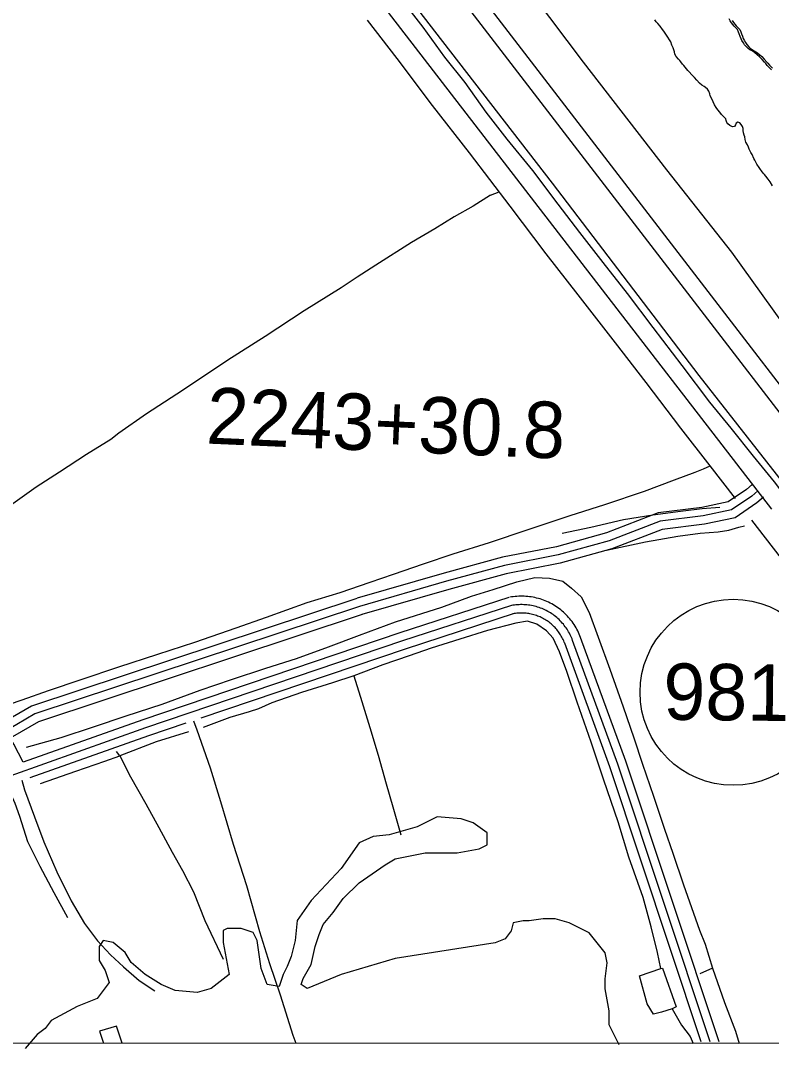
# Model space of a CAD drawing. Extents: x 3245246 to 3283090, y 806824 to 832173.
# Drawn here: x 3268806 to 3270136, y 812195 to 814018 of the extents above; entities that cross this region are included whole.
import ezdxf

# ---------------------------------------------------------------- set-up
doc = ezdxf.new("R2010")
doc.units = 0
for name, color, linetype in [('V-BORW-LINE', 7, 'Continuous'), ('V-GRID-FRAM', 7, 'Continuous'), ('V-LEVE-TOET', 7, 'Continuous'), ('V-ROAD-CNTR', 7, 'Continuous'), ('V-ROAD-IDEN', 7, 'Continuous'), ('V-SITE-STRC', 7, 'Continuous'), ('V-SITE-VEGE', 7, 'Continuous'), ('V-SURV-IDEN', 7, 'Continuous'), ('V-SURV-LINE', 7, 'Continuous'), ('V-TOPO-SHOR', 7, 'Continuous')]:
    doc.layers.add(name, color=color, linetype=linetype)

msp = doc.modelspace()

# ---------------------------------------------------------------- linework, layer by layer
at = {"layer": 'V-BORW-LINE'}
for points in [[(3270116.6, 813754.3), (3270114.5, 813757.4), (3270110.6, 813763.6), (3270107, 813770.4), (3270105.1, 813773.5), (3270101.8, 813780.6), (3270099.7, 813784.3), (3270096.9, 813790.2), (3270095.4, 813793.6), (3270093.6, 813797.9), (3270090.9, 813802.7), (3270089.9, 813807), (3270089.2, 813812.1), (3270087.7, 813815.2), (3270086.7, 813819.2), (3270086.3, 813823.5), (3270085.9, 813827), (3270084.7, 813830.4), (3270082.8, 813834.1), (3270079.9, 813837.1), (3270076.7, 813838.2), (3270073.9, 813836.4), (3270072.8, 813833.5), (3270070.9, 813830.6), (3270066.9, 813829.9), (3270062.2, 813831.8), (3270059, 813835.1), (3270056.9, 813837.4), (3270056, 813840.8), (3270055.3, 813843.9), (3270052.9, 813846.5), (3270050.3, 813849.3), (3270047.6, 813851.8), (3270044.7, 813855.7), (3270041.1, 813859.6), (3270038.4, 813863.9), (3270035.4, 813868.7), (3270033, 813873.8), (3270029.9, 813880.3), (3270027.8, 813884.8), (3270027.1, 813888), (3270025.3, 813892.8), (3270022.6, 813896.4), (3270019.4, 813899.2), (3270017, 813901.5), (3270012.9, 813903.9), (3270008.5, 813907.3), (3270003.8, 813912.3), (3269999.6, 813917.1), (3269997.6, 813919.6), (3269995.2, 813922.1), (3269990.2, 813927.4), (3269988.1, 813929.7), (3269985.4, 813932.8), (3269981, 813938.4), (3269978.6, 813940.9), (3269975.9, 813944.9), (3269973.9, 813947.1), (3269971.2, 813949.9), (3269967.1, 813954.4), (3269965.2, 813958.6), (3269964.2, 813962.6), (3269963, 813966), (3269961.8, 813969.7), (3269959.6, 813974.6), (3269958, 813980.5), (3269955.6, 813984.2), (3269952.3, 813989), (3269949, 813994.1), (3269945.5, 813999.4), (3269943.4, 814002.5), (3269938.9, 814008.5), (3269935, 814012.9), (3269932.1, 814016), (3269929.4, 814019.4)], [(3270066.7, 814018.2), (3270069.1, 814014.6), (3270073.8, 814008.9), (3270077.7, 814005), (3270080, 814002.5), (3270081.9, 813998), (3270083.1, 813994.8), (3270084.7, 813990.3), (3270086.2, 813986.3), (3270087.7, 813983.5), (3270090.4, 813979.2), (3270092.5, 813975.6), (3270096.4, 813971.4), (3270099, 813968.8), (3270101.9, 813966.6), (3270105.7, 813964.7), (3270109.8, 813962), (3270114.8, 813958.1), (3270118.9, 813954.2), (3270123.4, 813949.7), (3270127.8, 813944.6), (3270129.9, 813942.4), (3270132.6, 813939), (3270137.9, 813933.7)], [(3270138, 813725.3), (3270133.8, 813732.1), (3270130.2, 813737.1), (3270126.1, 813742.5), (3270124, 813745), (3270121.6, 813747.5), (3270118.7, 813751.8), (3270116.6, 813754.3)]]:
    msp.add_lwpolyline(points, dxfattribs=at)
at = {"layer": 'V-GRID-FRAM'}
msp.add_lwpolyline([(3249428.8, 830400), (3280833.3, 830386.3), (3280833.3, 812199.6), (3249412.9, 812213.3), (3249428.8, 830400)], dxfattribs=at)
at = {"layer": 'V-LEVE-TOET'}
for points in [[(3269309.8, 814296.6), (3269553.2, 813980.9), (3269747.4, 813729.8), (3270007.7, 813389), (3270212.9, 813126.4), (3270300.9, 813008.4), (3270316.5, 812980.3), (3270348.7, 812914.5), (3270515.4, 812529.7), (3270660.8, 812204)], [(3270853.7, 812203.9), (3270841.6, 812230.7), (3270740.7, 812469.9), (3270678, 812611.2), (3270607.7, 812771.2), (3270538.2, 812930.8), (3270513.8, 812999.4), (3270496.9, 813033), (3270482.6, 813057.4), (3270457.7, 813088.3), (3270385.9, 813179.7), (3270285.5, 813318.1), (3270193.6, 813429.3), (3270066.2, 813607.4), (3269950.8, 813753.5), (3269803.4, 813944.4), (3269654.7, 814141.9)]]:
    msp.add_lwpolyline(points, dxfattribs=at)
at = {"layer": 'V-ROAD-CNTR'}
for points in [[(3269299.2, 814237.7), (3269774.1, 813621.1), (3270136.2, 813151.8)], [(3270102, 813195.4), (3270092.1, 813186.5), (3270059.8, 813164.8), (3270012.8, 813154.8), (3269935.4, 813144.9), (3269844, 813110), (3269755, 813085.1), (3269659.5, 813066.3), (3269556.3, 813038.3), (3269402.1, 812993.6)], [(3270112.1, 813184.3), (3270101.3, 813174.6), (3270065.7, 813150.7), (3270015.3, 813140), (3269939.1, 813130.3), (3269848.7, 813095.8), (3269758.5, 813070.5), (3269662.9, 813051.7), (3269560.4, 813023.8), (3269406.3, 812979.2)], [(3270122.1, 813173.1), (3270110.6, 813162.7), (3270071.7, 813136.6), (3270017.8, 813125.2), (3269942.8, 813115.6), (3269853.4, 813081.5), (3269762, 813055.9), (3269666.3, 813037), (3269564.4, 813009.4), (3269410.5, 812964.8)], [(3269401.6, 812993.5), (3268824.9, 812802.2), (3268791.4, 812783), (3268758.5, 812764)], [(3269670.7, 812995), (3269477.9, 812932.2), (3269022.3, 812778), (3268810.4, 812702.8)], [(3269797.9, 812924.3), (3269796.8, 812927.1), (3269795.6, 812930), (3269794.3, 812933), (3269792.9, 812935.9), (3269791.4, 812938.7), (3269789.9, 812941.5), (3269788.2, 812944.3), (3269786.5, 812947), (3269784.7, 812949.6), (3269782.8, 812952.2), (3269780.9, 812954.8), (3269778.9, 812957.3), (3269776.8, 812959.7), (3269774.6, 812962.1), (3269772.4, 812964.4), (3269770.1, 812966.7), (3269767.8, 812968.8), (3269765.4, 812971), (3269762.9, 812973), (3269760.4, 812975), (3269757.8, 812976.9), (3269755.1, 812978.7), (3269752.4, 812980.4), (3269749.7, 812982.1), (3269746.9, 812983.7), (3269744.1, 812985.2), (3269741.2, 812986.6), (3269738.3, 812987.9), (3269735.3, 812989.2), (3269732.3, 812990.3), (3269729.3, 812991.4), (3269726.3, 812992.4), (3269723.2, 812993.3), (3269720.1, 812994.1), (3269717, 812994.9), (3269713.8, 812995.5), (3269710.6, 812996.1), (3269707.5, 812996.5), (3269704.3, 812996.9), (3269701.1, 812997.1), (3269697.9, 812997.3), (3269694.7, 812997.4), (3269691.5, 812997.4), (3269688.3, 812997.3), (3269685.1, 812997.1), (3269681.9, 812996.8), (3269678.7, 812996.4), (3269675.5, 812996), (3269672.7, 812995.5)], [(3269675.3, 812980.7), (3269482.6, 812918), (3269027.2, 812763.8), (3268727.9, 812657.6), (3268524, 812586.4), (3267985.6, 812407), (3267401, 812210.6)], [(3269406.3, 812979.2), (3268831, 812788.5), (3268798.9, 812770), (3268763.9, 812749.8)], [(3269680, 812966.4), (3269487.3, 812903.7), (3269125, 812781.1)], [(3269783.9, 812919), (3269782.9, 812921.5), (3269781.8, 812924.1), (3269780.7, 812926.6), (3269779.5, 812929.1), (3269778.2, 812931.6), (3269776.8, 812934), (3269775.4, 812936.4), (3269773.9, 812938.8), (3269772.4, 812941.1), (3269770.8, 812943.3), (3269769.1, 812945.5), (3269767.4, 812947.7), (3269765.5, 812949.8), (3269763.7, 812951.9), (3269761.8, 812953.9), (3269759.8, 812955.8), (3269757.7, 812957.7), (3269755.7, 812959.5), (3269753.5, 812961.3), (3269751.3, 812963), (3269749.1, 812964.6), (3269746.8, 812966.2), (3269744.5, 812967.7), (3269742.1, 812969.1), (3269739.7, 812970.5), (3269737.2, 812971.8), (3269734.7, 812973), (3269732.2, 812974.2), (3269729.7, 812975.3), (3269727.1, 812976.3), (3269724.5, 812977.2), (3269721.8, 812978.1), (3269719.2, 812978.9), (3269716.5, 812979.6), (3269713.8, 812980.2), (3269711, 812980.8), (3269708.3, 812981.2), (3269705.6, 812981.6), (3269702.8, 812981.9), (3269700, 812982.2), (3269697.3, 812982.3), (3269694.5, 812982.4), (3269691.7, 812982.4), (3269688.9, 812982.3), (3269686.2, 812982.1), (3269683.4, 812981.9), (3269680.7, 812981.6), (3269677.9, 812981.2), (3269675.3, 812980.7)], [(3269769.8, 812913.6), (3269768.9, 812916), (3269768, 812918.2), (3269767.1, 812920.3), (3269766.1, 812922.4), (3269765, 812924.5), (3269763.8, 812926.6), (3269762.6, 812928.6), (3269761.4, 812930.6), (3269760.1, 812932.5), (3269758.7, 812934.4), (3269757.3, 812936.3), (3269755.8, 812938.1), (3269754.3, 812939.9), (3269752.7, 812941.6), (3269751.1, 812943.3), (3269749.4, 812944.9), (3269747.7, 812946.5), (3269745.9, 812948.1), (3269744.1, 812949.6), (3269742.3, 812951), (3269740.4, 812952.4), (3269738.5, 812953.7), (3269736.5, 812955), (3269734.5, 812956.2), (3269732.5, 812957.4), (3269730.4, 812958.5), (3269728.3, 812959.5), (3269726.2, 812960.5), (3269724, 812961.4), (3269721.8, 812962.2), (3269719.6, 812963), (3269717.4, 812963.8), (3269715.1, 812964.4), (3269712.9, 812965), (3269710.6, 812965.6), (3269708.3, 812966), (3269706, 812966.4), (3269703.7, 812966.7), (3269701.3, 812967), (3269699, 812967.2), (3269696.7, 812967.3), (3269694.3, 812967.4), (3269692, 812967.4), (3269689.6, 812967.3), (3269687.3, 812967.2), (3269685, 812967), (3269682.6, 812966.7), (3269680.3, 812966.4), (3269677.9, 812965.9)], [(3269411, 812965), (3268837.2, 812774.7), (3268806.3, 812757), (3268787, 812745.8)], [(3270011.9, 812207), (3269850.1, 812694.7), (3269769.8, 812913.8)], [(3270027.7, 812207), (3269864.2, 812699.6), (3269783.9, 812919)], [(3270043.6, 812207), (3269878.4, 812704.6), (3269797.9, 812924.1)], [(3269098.3, 812772.1), (3269032.1, 812749.6), (3268822, 812675.1)], [(3269111.9, 812776.1), (3269117.6, 812760.6), (3269141.3, 812692.8), (3269160, 812633.1), (3269182, 812557.7), (3269205.8, 812484.2), (3269228.9, 812403), (3269246.4, 812345.8), (3269265.3, 812290.3), (3269287.9, 812219.1), (3269293.3, 812204.6)], [(3268810.4, 812702.8), (3268793.4, 812735.2), (3268787, 812745.8)], [(3268807.9, 812671.3), (3268812.7, 812654.1), (3268830.2, 812605.9), (3268847, 812561.6), (3268869.7, 812508.6), (3268895, 812457.2), (3268919, 812416.9), (3268942.1, 812386), (3268965, 812361.1), (3268988.1, 812339.8), (3269015.9, 812316.1), (3269043.2, 812297.6)]]:
    msp.add_lwpolyline(points, dxfattribs=at)
at = {"layer": 'V-ROAD-IDEN'}
msp.add_circle((3270068.4, 812827), 165, dxfattribs=at)
at = {"layer": 'V-SITE-STRC'}
msp.add_lwpolyline([(3268985.7, 812204.7), (3268975.4, 812235.1), (3268945.2, 812226.2), (3268952.6, 812204.8)], dxfattribs=at)
at = {"layer": 'V-SITE-VEGE'}
for p, q in [((3270062.8, 814017.8), (3270061.3, 814021.2)), ((3270065.2, 814014.1), (3270062.8, 814017.8)), ((3270070, 814008.5), (3270065.2, 814014.1)), ((3270073.8, 814004.6), (3270070, 814008.5)), ((3270076.2, 814002.1), (3270073.8, 814004.6)), ((3270078, 813997.5), (3270076.2, 814002.1)), ((3270079.2, 813994.4), (3270078, 813997.5)), ((3270080.8, 813989.8), (3270079.2, 813994.4)), ((3270082.3, 813985.9), (3270080.8, 813989.8)), ((3270083.8, 813983), (3270082.3, 813985.9)), ((3270086.5, 813978.8), (3270083.8, 813983)), ((3270088.7, 813975.1), (3270086.5, 813978.8)), ((3270092.5, 813970.9), (3270088.7, 813975.1)), ((3270095.1, 813968.4), (3270092.5, 813970.9)), ((3270098.1, 813966.2), (3270095.1, 813968.4)), ((3270101.9, 813964.3), (3270098.1, 813966.2)), ((3270106, 813961.5), (3270101.9, 813964.3)), ((3270110.9, 813957.6), (3270106, 813961.5)), ((3270115.1, 813953.7), (3270110.9, 813957.6)), ((3270119.5, 813949.3), (3270115.1, 813953.7)), ((3270123.9, 813944.2), (3270119.5, 813949.3)), ((3270126, 813942), (3270123.9, 813944.2)), ((3270128.7, 813938.6), (3270126, 813942)), ((3270134, 813933.3), (3270128.7, 813938.6)), ((3270136.6, 813930.8), (3270134, 813933.3))]:
    msp.add_line(p, q, dxfattribs=at)
at = {"layer": 'V-SURV-LINE'}
for points in [[(3269345.8, 814419.9), (3270382.2, 813071.1)], [(3270358.4, 813052.8), (3269322, 814401.6)]]:
    msp.add_lwpolyline(points, dxfattribs=at)
at = {"layer": 'V-TOPO-SHOR'}
for p, q in [((3269638.5, 813708.8), (3269653.7, 813714.5)), ((3270032, 812337.7), (3270009.5, 812327.6))]:
    msp.add_line(p, q, dxfattribs=at)
for points in [[(3269474.4, 814063.1), (3269518.3, 814006.6), (3269556.6, 813953.1), (3269592.8, 813908.5), (3269630.1, 813855.7), (3269667.2, 813808.1), (3269712.5, 813752)], [(3270072.3, 813170.8), (3270027.7, 813228.4), (3269975.5, 813295.4), (3269913.9, 813376.5), (3269859.6, 813446.5), (3269793.6, 813531.8), (3269737.1, 813604.7), (3269673.3, 813688.9), (3269601.2, 813783.6), (3269535.8, 813867.5), (3269473.2, 813950.9), (3269420.4, 814019.1)], [(3269712.5, 813752), (3269757.8, 813692.7), (3269796.2, 813642.6), (3269837.4, 813588.9), (3269880.4, 813534), (3269925.8, 813473.6), (3269977.6, 813406.5), (3270026.3, 813341.5), (3270064.3, 813295.4), (3270103.8, 813245.6), (3270141.1, 813200.4), (3270178.8, 813150.6)], [(3269638.5, 813708.8), (3269607.4, 813689), (3269574.2, 813670.1), (3269539.5, 813649), (3269498.5, 813624.5), (3269435, 813584.4), (3269402.3, 813563.4), (3269373.4, 813544.5), (3269307.9, 813503.2), (3269239, 813457.7), (3269173.1, 813416), (3269119.1, 813380), (3269082.2, 813355.7)], [(3269082.2, 813355.7), (3269028.5, 813320.7), (3268979.7, 813286.7), (3268965.3, 813275.5), (3268922.2, 813248.9), (3268874.4, 813217.2), (3268833.4, 813190.8), (3268792.1, 813161.4), (3268752.7, 813136.3), (3268695.5, 813097.9), (3268640.7, 813061.2), (3268584, 813024.4), (3268509.3, 812974.8), (3268448.2, 812931.8)], [(3269519.3, 813054.9), (3269572, 813072.4), (3269636.6, 813092.8), (3269705.3, 813115.7), (3269779.7, 813140.3), (3269841.2, 813160.2), (3269911.2, 813183.6), (3269964.6, 813203.8), (3270001.1, 813217.4), (3270015.9, 813223.3), (3270027.7, 813228.4)], [(3269765.2, 813109.4), (3269816.2, 813120), (3269873.9, 813133.4), (3269925.8, 813141.6), (3269974.9, 813148.3), (3270013.7, 813152.7), (3270044.7, 813155)], [(3270479.4, 812398.5), (3270440.2, 812486.9), (3270408, 812557.6), (3270375.9, 812630.8), (3270337.7, 812715), (3270304.8, 812788.9), (3270274.1, 812857), (3270249.2, 812915.7), (3270230.2, 812952.1), (3270202.1, 812995.7), (3270163.9, 813051), (3270101.5, 813132.4)], [(3269844, 813079), (3269912.9, 813093.8), (3269970.4, 813103.9), (3270010.1, 813109.3), (3270041.8, 813111.2), (3270060.6, 813114.2), (3270078.2, 813120), (3270088.4, 813122)], [(3269187.7, 812941), (3269241.4, 812960.2), (3269313.5, 812985.9), (3269372.1, 813004.2), (3269425, 813022.4), (3269466.6, 813036.3), (3269519.3, 813054.9)], [(3269351.5, 812907.4), (3269406.4, 812928.4), (3269469.7, 812952), (3269551.9, 812977.9), (3269604.7, 812997.6), (3269643.1, 813009.4), (3269685.1, 813023.1), (3269717, 813030.3), (3269742.9, 813029.3), (3269766.5, 813024.2), (3269782, 813011.3), (3269799.2, 812996.4), (3269813.3, 812968.5), (3269829.2, 812924.8)], [(3269940.2, 812336.9), (3269934.5, 812365.5), (3269923.2, 812410.9), (3269909.1, 812463.1), (3269883.7, 812534.7), (3269864.4, 812597.2), (3269839.2, 812671.3), (3269816.5, 812738.6), (3269791.8, 812809.6), (3269773.6, 812864.1), (3269760.6, 812898.8), (3269749.3, 812922.9), (3269737.5, 812936.2), (3269720.4, 812947.5), (3269704.1, 812952.8), (3269683.3, 812949.7), (3269633.1, 812936.6), (3269584.1, 812921.4), (3269533.1, 812905), (3269494, 812891.4), (3269447.8, 812875.6), (3269396.4, 812856.2)], [(3268744, 812791.4), (3268808.2, 812813.7), (3268854.9, 812829.9), (3268913, 812849.6), (3268979.6, 812872.3), (3269048.5, 812894.5), (3269114.1, 812916), (3269187.7, 812941)], [(3269829.2, 812924.8), (3269849.7, 812867.8), (3269873.3, 812801.2), (3269892.3, 812746.1), (3269907.9, 812699.7), (3269927.2, 812643), (3269946.8, 812584.4), (3269961.6, 812541.9), (3269980.5, 812485.7)], [(3268815.9, 812729.9), (3268877.3, 812746.5), (3268934.9, 812765.6), (3268992.6, 812785.2), (3269056.6, 812805.6), (3269123.6, 812830.6), (3269179.2, 812849.5), (3269240.3, 812869.8), (3269294.4, 812886.8), (3269351.5, 812907.4)], [(3269396.4, 812856.2), (3269358.3, 812843.7), (3269303.1, 812826.3), (3269250.6, 812808), (3269227.1, 812797.8), (3269210.5, 812792.4), (3269176.5, 812782.5), (3269129.1, 812764.2)], [(3269396.4, 812856.2), (3269410.4, 812810.7), (3269424.5, 812764.4), (3269439.5, 812715.3), (3269453.6, 812664.7), (3269465.5, 812623.6), (3269479.5, 812574.1)], [(3269102.9, 812756.7), (3269046, 812739.3), (3268981.4, 812714.5), (3268975.4, 812721.9)], [(3268840.6, 812665), (3268903.5, 812686.9), (3268955.1, 812704.8), (3268981.4, 812714.5)], [(3268981.4, 812714.5), (3269000.5, 812677), (3269027.8, 812629.4), (3269050.7, 812587.4), (3269074.4, 812543.7), (3269092.3, 812510.9), (3269111.7, 812473), (3269132.2, 812422.2), (3269164.4, 812353.4)], [(3268889.5, 812427.1), (3268865.1, 812471.2), (3268840.4, 812517.8), (3268818.6, 812561.5), (3268804.2, 812606.8), (3268795.7, 812629.6), (3268789, 812645.9), (3268732.9, 812628.9), (3268702.4, 812615.2), (3268673.7, 812597.7), (3268647.1, 812583.1)], [(3269866.4, 812202), (3269848.6, 812237.4), (3269848.7, 812262.2), (3269841.6, 812301.2), (3269841.6, 812319), (3269845.1, 812347.3), (3269841.6, 812365.1), (3269827.4, 812382.8), (3269813.3, 812400.5), (3269777.8, 812418.3), (3269753, 812425.4), (3269731.7, 812425.4), (3269706.9, 812421.8), (3269696.3, 812421.8), (3269678.5, 812418.3), (3269675, 812404.1), (3269664.3, 812390), (3269646.6, 812382.9), (3269469.3, 812354.6), (3269373.6, 812326.3), (3269313.3, 812301.5), (3269302.7, 812308.6), (3269306.2, 812319.2), (3269320.4, 812344), (3269327.5, 812375.9), (3269334.6, 812397.2), (3269341.7, 812414.9), (3269359.5, 812436.2), (3269377.2, 812461), (3269405.6, 812489.3), (3269451.7, 812521.2), (3269469.4, 812531.8), (3269522.6, 812542.5), (3269579.3, 812542.4), (3269618.3, 812549.5), (3269632.5, 812556.6), (3269632.5, 812577.9), (3269607.7, 812595.6), (3269586.4, 812602.7), (3269543.9, 812606.3), (3269508.4, 812588.6), (3269483.6, 812581.5), (3269458.8, 812574.4), (3269430.4, 812570.9), (3269405.6, 812560.2), (3269373.7, 812514.2), (3269320.5, 812457.5), (3269295.6, 812422), (3269292.1, 812386.6), (3269285, 812358.2), (3269277.9, 812340.5), (3269270.8, 812326.3), (3269263.7, 812305), (3269242.4, 812308.6), (3269231.8, 812337), (3269224.7, 812386.6), (3269217.6, 812400.8), (3269196.4, 812407.9), (3269171.6, 812407.9), (3269164.5, 812404.3), (3269164.5, 812383.1), (3269175.1, 812326.3), (3269143.1, 812301.5), (3269118.3, 812294.5), (3269079.3, 812298), (3269054.5, 812308.7), (3269026.2, 812326.4), (3269001.4, 812347.7), (3268990.7, 812365.4), (3268969.5, 812383.2), (3268951.7, 812386.7), (3268944.6, 812376.1), (3268944.6, 812351.3), (3268955.3, 812333.5), (3268962.3, 812312.3), (3268941.1, 812283.9), (3268905.6, 812269.7), (3268859.5, 812244.9), (3268848.9, 812230.8), (3268834.7, 812220.1), (3268813.4, 812195.3)], [(3269980.5, 812485.7), (3270008.9, 812405), (3270019, 812380.3), (3270032, 812337.7), (3270052.8, 812276.7), (3270072.4, 812225.7), (3270078.8, 812204.3)], [(3269960.2, 812265.7), (3269941.5, 812259.4), (3269927.3, 812256.1), (3269915.7, 812274.5), (3269902.2, 812323.9), (3269940.2, 812336.9), (3269943.2, 812337.9), (3269967.3, 812269.1), (3269960.2, 812265.7)], [(3269960.2, 812265.7), (3269977.1, 812236.8), (3269992.3, 812216.6), (3269997.5, 812204.3)]]:
    msp.add_lwpolyline(points, dxfattribs=at)

# ---------------------------------------------------------------- texts
at = {"layer": 'V-ROAD-IDEN'}
msp.add_text('981', height=100, rotation=359.3568, dxfattribs=at).set_placement((3269944.2, 812778.4))
at = {"layer": 'V-SURV-IDEN'}
msp.add_text('2243+30.8', height=100, rotation=357.5485, dxfattribs=at).set_placement((3269133.4, 813268.1))

doc.saveas('drawing.dxf')
